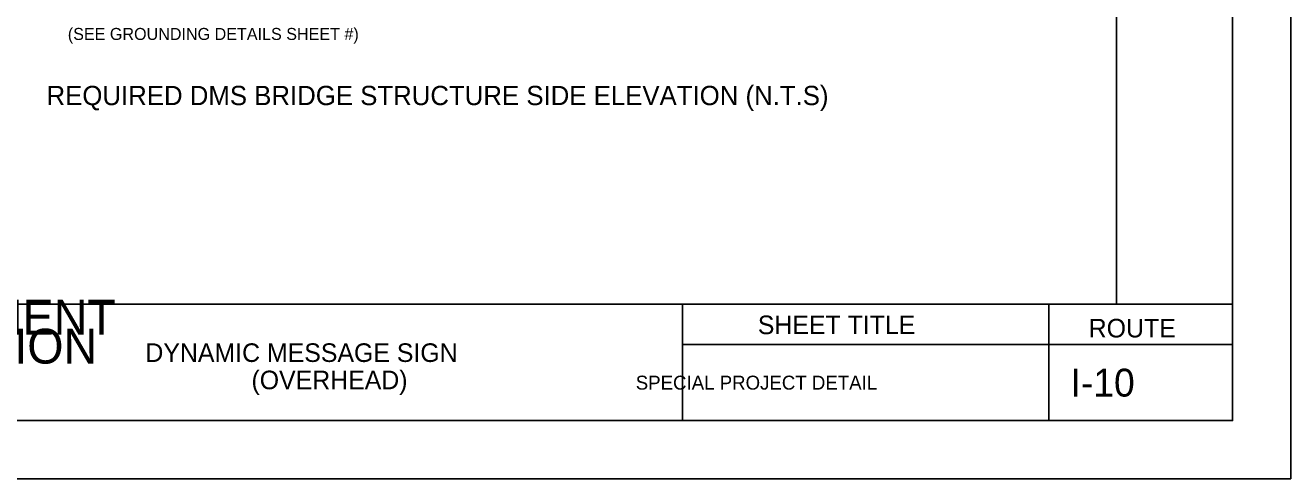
# Model space of a CAD drawing. Extents: x 515543 to 517243, y 661761 to 662861.
# Drawn here: x 516698 to 517243, y 661761 to 661956 of the extents above; entities that cross this region are included whole.
import ezdxf

# ---------------------------------------------------------------- set-up
doc = ezdxf.new("R2010")
doc.units = 0
for name, color, linetype in [('ANNO-SHT', 7, 'Continuous'), ('ANNO-TXT', 7, 'Continuous'), ('C-TOPO-TEXT', 7, 'Continuous'), ('Level 6', 7, 'Continuous'), ('Level 62', 7, 'Continuous'), ('Level 8', 7, 'Continuous'), ('SHT-BDR', 7, 'Continuous'), ('SHT-BNDRY', 7, 'Continuous')]:
    doc.layers.add(name, color=color, linetype=linetype)

msp = doc.modelspace()

# ---------------------------------------------------------------- linework, layer by layer
at = {"layer": 'ANNO-TXT'}
for p, q in [((516980.81, 661818.41), (517138.45, 661818.41)), ((517138.45, 661818.41), (517217.52, 661818.41))]:
    msp.add_line(p, q, dxfattribs=at)
at = {"layer": 'Level 6'}
msp.add_line((517217.52, 661835.77), (516980.81, 661835.77), dxfattribs=at)
at = {"layer": 'Level 62'}
msp.add_lwpolyline([(515542.51, 661760.72), (517242.52, 661760.72), (517242.52, 662860.72), (515542.51, 662860.72)], close=True, dxfattribs=at)
at = {"layer": 'SHT-BDR'}
msp.add_lwpolyline([(515667.5, 661835.77), (517167.5, 661835.77), (517167.5, 662785.77), (515667.5, 662785.77)], close=True, dxfattribs=at)
at = {"layer": 'SHT-BNDRY'}
for p, q in [((516980.81, 661785.72), (516980.81, 661835.77)), ((517138.45, 661785.72), (517138.45, 661835.77))]:
    msp.add_line(p, q, dxfattribs=at)
msp.add_lwpolyline([(515605.01, 661785.72), (517217.52, 661785.72), (517217.52, 662835.72), (515605.01, 662835.72)], close=True, dxfattribs=at)

# ---------------------------------------------------------------- texts
at = {"layer": 'ANNO-SHT'}
for s, height, p in [('         SPECIAL PROJECT DETAIL         ', 6, (516940.64, 661799.06)), ('  I-10  ', 12, (517138.85, 661796.06))]:
    msp.add_text(s, height=height, dxfattribs=at).set_placement(p)
at = {"layer": 'ANNO-TXT'}
for s, p in [('ALABAMA DEPARTMENT', (516498.51, 661822.77)), ('OF TRANSPORTATION', (516510.56, 661810.27))]:
    msp.add_text(s, height=15, rotation=360, dxfattribs=at).set_placement(p)
for s, p in [('SHEET TITLE', (517013.24, 661822.93)), ('ROUTE', (517155.61, 661821.52))]:
    msp.add_text(s, height=8, dxfattribs=at).set_placement(p)
at = {"layer": 'C-TOPO-TEXT'}
for s, p in [('DYNAMIC MESSAGE SIGN ', (516749.73, 661810.97)), ('(OVERHEAD)', (516795.36, 661799.22))]:
    msp.add_text(s, height=8, rotation=0.0003, dxfattribs=at).set_placement(p)
at = {"layer": 'Level 8'}
msp.add_text('(SEE GROUNDING DETAILS SHEET #)', height=5.184, dxfattribs=at).set_placement((516716.34, 661949.55))
msp.add_text('REQUIRED DMS BRIDGE STRUCTURE SIDE ELEVATION (N.T.S)', height=8.2944, rotation=360, dxfattribs=at).set_placement((516707.19, 661921.51))

doc.saveas('drawing.dxf')
